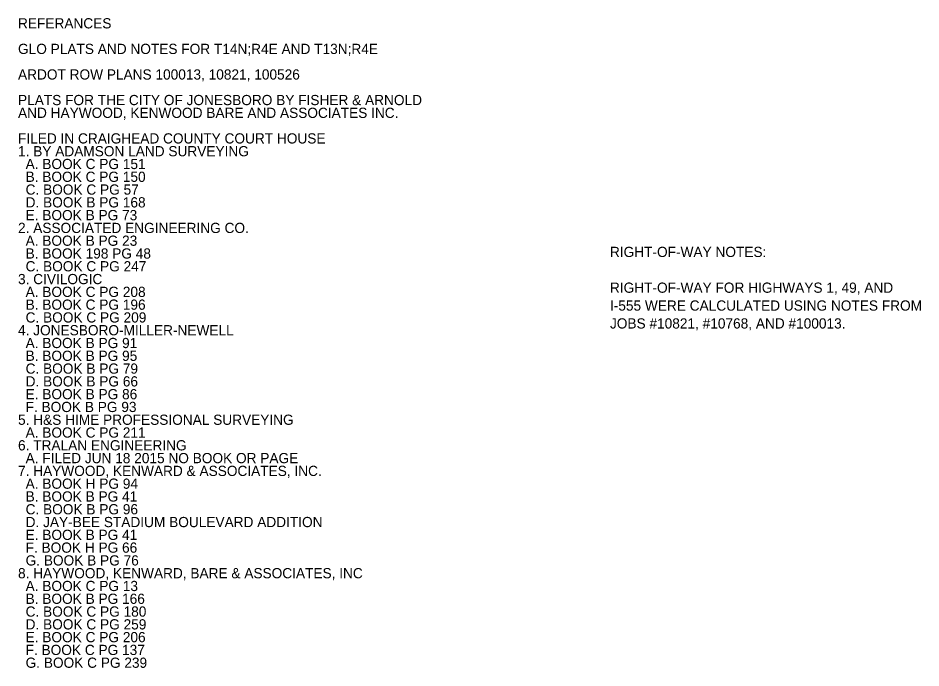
# Model space of a CAD drawing. Extents: x 1431802 to 1457777, y 1852108 to 1876350.
# Drawn here: x 1431802 to 1432465, y 1870938 to 1871415 of the extents above; entities that cross this region are included whole.
import ezdxf

# ---------------------------------------------------------------- set-up
doc = ezdxf.new("R2010")
doc.units = 0
doc.layers.add('Default', color=7, linetype='Continuous')

msp = doc.modelspace()

# ---------------------------------------------------------------- texts
at = {"layer": 'Default'}
for s, p in [('REFERANCES', (1431801.92, 1871407.24)), ('GLO PLATS AND NOTES FOR T14N;R4E AND T13N;R4E', (1431801.92, 1871388.46)), ('ARDOT ROW PLANS 100013, 10821, 100526', (1431801.92, 1871369.68)), ('PLATS FOR THE CITY OF JONESBORO BY FISHER & ARNOLD', (1431801.92, 1871350.9)), ('AND HAYWOOD, KENWOOD BARE AND ASSOCIATES INC.', (1431801.92, 1871341.51)), ('FILED IN CRAIGHEAD COUNTY COURT HOUSE', (1431801.92, 1871322.73)), ('1. BY ADAMSON LAND SURVEYING', (1431801.92, 1871313.34)), ('  A. BOOK C PG 151', (1431801.92, 1871303.95)), ('  B. BOOK C PG 150', (1431801.92, 1871294.56)), ('  C. BOOK C PG 57', (1431801.92, 1871285.18)), ('  D. BOOK B PG 168', (1431801.92, 1871275.79)), ('  E. BOOK B PG 73', (1431801.92, 1871266.4)), ('2. ASSOCIATED ENGINEERING CO.', (1431801.92, 1871257.01)), ('  A. BOOK B PG 23', (1431801.92, 1871247.62)), ('  B. BOOK 198 PG 48', (1431801.92, 1871238.23)), ('RIGHT-OF-WAY NOTES:', (1432236.33, 1871239.38)), ('  C. BOOK C PG 247', (1431801.92, 1871228.84)), ('3. CIVILOGIC', (1431801.92, 1871219.45)), ('RIGHT-OF-WAY FOR HIGHWAYS 1, 49, AND ', (1432236.33, 1871213.13)), ('  A. BOOK C PG 208', (1431801.92, 1871210.06)), ('  B. BOOK C PG 196', (1431801.92, 1871200.67)), ('I-555 WERE CALCULATED USING NOTES FROM ', (1432236.33, 1871200.01)), ('  C. BOOK C PG 209', (1431801.92, 1871191.28)), ('JOBS #10821, #10768, AND #100013.', (1432236.33, 1871186.88)), ('4. JONESBORO-MILLER-NEWELL', (1431801.92, 1871181.89)), ('  A. BOOK B PG 91', (1431801.92, 1871172.5)), ('  B. BOOK B PG 95', (1431801.92, 1871163.11)), ('  C. BOOK B PG 79', (1431801.92, 1871153.72)), ('  D. BOOK B PG 66', (1431801.92, 1871144.33)), ('  E. BOOK B PG 86', (1431801.92, 1871134.94)), ('  F. BOOK B PG 93', (1431801.92, 1871125.55)), ('5. H&S HIME PROFESSIONAL SURVEYING', (1431801.92, 1871116.16)), ('  A. BOOK C PG 211', (1431801.92, 1871106.77)), ('6. TRALAN ENGINEERING', (1431801.92, 1871097.38)), ('  A. FILED JUN 18 2015 NO BOOK OR PAGE', (1431801.92, 1871087.99)), ('7. HAYWOOD, KENWARD & ASSOCIATES, INC.', (1431801.92, 1871078.6)), ('  A. BOOK H PG 94', (1431801.92, 1871069.21)), ('  B. BOOK B PG 41', (1431801.92, 1871059.82)), ('  C. BOOK B PG 96', (1431801.92, 1871050.43)), ('  D. JAY-BEE STADIUM BOULEVARD ADDITION', (1431801.92, 1871041.04)), ('  E. BOOK B PG 41', (1431801.92, 1871031.65)), ('  F. BOOK H PG 66', (1431801.92, 1871022.26)), ('  G. BOOK B PG 76', (1431801.92, 1871012.87)), ('8. HAYWOOD, KENWARD, BARE & ASSOCIATES, INC', (1431801.92, 1871003.48)), ('  A. BOOK C PG 13', (1431801.92, 1870994.09)), ('  B. BOOK B PG 166', (1431801.92, 1870984.7)), ('  C. BOOK C PG 180', (1431801.92, 1870975.31)), ('  D. BOOK C PG 259', (1431801.92, 1870965.92)), ('  E. BOOK C PG 206', (1431801.92, 1870956.53)), ('  F. BOOK C PG 137', (1431801.92, 1870947.14)), ('  G. BOOK C PG 239', (1431801.92, 1870937.75))]:
    msp.add_text(s, height=7.5, dxfattribs=at).set_placement(p)

doc.saveas('drawing.dxf')
